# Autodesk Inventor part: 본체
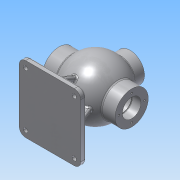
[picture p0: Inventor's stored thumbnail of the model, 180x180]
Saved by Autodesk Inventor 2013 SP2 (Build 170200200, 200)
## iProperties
Created: 2018-06
Part Number: 본체
Material: 알루미늄 6061
Document SubType Name: Modeling
Designer: Administrator
Density: 2.71 g/cm^3
Mass: 1509.84 g
Surface Area: 1154.8 cm^2
Volume: 557.135 cm^3
Author: Administrator
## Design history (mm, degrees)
sketch "스케치1"
  geometry: L1 (-68, 0)-(68, 0); L2 (-42.988, 31)-(-68, 31); L3 (-68, 31)-(-68, 17.5); L4 (-68, 17.5)-(-39.278, 17.5); L5 (42.988, 31)-(68, 31); L6 (68, 31)-(68, 17.5); L7 (68, 17.5)-(39.278, 17.5); A1 r 53 centre (0, 0) between (42.988, 31) and (-42.988, 31); A2 r 43 centre (0, 0) between (39.278, 17.5) and (-39.278, 17.5); 2 further points
  constraints: 14 end point, 4 perpendicular, 4 point on circle, 3 coincident, 2 centre point, 2 horizontal alignment, 2 parallel, 1 horizontal, 1 midpoint, 1 vertical alignment
  dimensions: "d0" = 106 diameter of A1; "d1" = 86 diameter of A2; "d2" = 136 distance of L1.start L1.end; "d3" = 136 distance between parallel lines of L3 L6; "d4" = 62 diameter of L2 L1; "d5" = 35 diameter of L4 L1
revolve "회전1" sketch "스케치1" stored, may be unused: angle "d6" = 90 deg
node "작업 평면1"
sketch "스케치2"
  geometry: L1 (-57.5, -62.5)-(57.5, -62.5); L2 (57.5, -62.5)-(57.5, 62.5); L3 (57.5, 62.5)-(-57.5, 62.5); L4 (-57.5, 62.5)-(-57.5, -62.5); L5 (-57.5, -62.5)-(57.5, 62.5); L6 (57.5, -62.5)-(-57.5, 62.5); 1 further point
  constraints: 12 end point, 2 midpoint, 2 parallel, 1 horizontal, 1 perpendicular
  dimensions: "d8" = 115 distance of L3.end L2.end; "d9" = 125 distance of L2.end L1.end
extrude "돌출1" join sketch "스케치2" distance "d10" = 10; taper "d11" = 0 deg
sketch "스케치4"
  geometry: L1 (57.5, -75)-(-57.5, -75) reference; L2 (33.719, -40.891)-(47.5, -75); L3 (57.5, -85)-(57.5, -75) reference; L4 (-57.5, -85)-(-57.5, -75) reference; L5 (-33.654, -40.944)-(-47.414, -75); L6 (-47.414, -75)-(47.5, -75); A1 r 53 centre (0, 0) between (42.988, 31) and (42.988, -31) reference; 1 further point
  constraints: 6 end point, 2 point on circle, 2 point on line, 1 collinear
  dimensions: "d12" = 22 deg angle of L3 L2; "d13" = 10 distance of L1.start L2.end; "d16" = 10.08634 distance of L1.end L5.end; "d17" = 22 deg angle of L4 L5
node "작업 평면2"
sketch "스케치5"
  geometry: C1 r 27 at (0, 0); 1 further point
  constraints: 1 centre point, 1 coincident
  dimensions: "d19" = 54 diameter of C1
extrude "돌출2" join sketch "스케치5" stored distance "d21" = 10; taper "d22" = 0 deg
hole "구멍1" diameter "d25" = 26; stored, may be unused: countersink angle "d29" = 90 deg, drill point angle "d31" = 0 deg; dims "d26" = 6, "d27" = 4, "d28" = 2, "d30" = 8, "d32" = 10, "d33" = 10
sketch "스케치6" dims "d34" = 45
  geometry: C1 r 31 at (0, 0) reference; C2 r 17.5 at (0, 0) reference; 2 further points
  constraints: 2 vertical alignment, 1 coincident, 2 other
hole "구멍2" sketch "스케치6" at (0, 22.5) diameter "d35" = 3.242; stored, may be unused: countersink angle "d39" = 90 deg, drill point angle "d41" = 118 deg; dims "d36" = 12, "d37" = 4, "d38" = 2, "d40" = 15
sketch "스케치7" dims "d45" = 48
  geometry: C1 r 17.5 at (0, 0) reference; C2 r 31 at (0, 0) reference; 2 further points
  constraints: 2 vertical alignment, 1 coincident, 2 other
hole "구멍3" sketch "스케치7" at (0, 24) diameter "d46" = 3.242; stored, may be unused: countersink angle "d50" = 90 deg, drill point angle "d52" = 118 deg; dims "d47" = 16, "d48" = 4, "d49" = 2, "d51" = 19
sketch "스케치9"
  geometry: L1 (57.5, 62.5)-(-57.5, 62.5) reference; L2 (-4, -52.5)-(4, -52.5); L3 (4, -52.5)-(4, 52.5); L4 (4, 52.5)-(-4, 52.5); L5 (-4, 52.5)-(-4, -52.5); L6 (-4, -52.5)-(4, 52.5); L7 (4, -52.5)-(-4, 52.5); 1 further point
  constraints: 12 end point, 2 midpoint, 2 parallel, 1 horizontal, 1 perpendicular
  dimensions: "d57" = 8 distance of L4.end L3.end; "d58" = 10 distance between parallel lines of L1 L4
extrude "돌출3" join sketch "스케치9" stored distance "d59" = 10; taper "d60" = 0 deg
feature "면 기울기1" dims angle "d61" = 22 deg
sketch "스케치10"
  geometry: L1 (57.5, -62.5)-(57.5, 62.5) reference; L2 (-47.5, 4)-(47.5, 4); L3 (47.5, 4)-(47.5, -4); L4 (47.5, -4)-(-47.5, -4); L5 (-47.5, -4)-(-47.5, 4); L6 (-47.5, 4)-(47.5, -4); L7 (47.5, 4)-(-47.5, -4); 1 further point
  constraints: 12 end point, 2 midpoint, 2 parallel, 1 horizontal, 1 perpendicular
  dimensions: "d62" = 8 distance of L2.end L3.end; "d63" = 10 distance between parallel lines of L1 L3
extrude "돌출4" join sketch "스케치10" stored distance "d64" = 10; taper "d65" = 0 deg
feature "면 기울기2" dims angle "d66" = 22 deg
sketch "스케치11" dims "d67" = 40
  geometry: C1 r 13 at (0, 0) reference; C2 r 27 at (0, 0) reference; 2 further points
  constraints: 2 vertical alignment, 1 coincident, 2 other
hole "구멍4" sketch "스케치11" at (0, 20) diameter "d68" = 3.242; stored, may be unused: countersink angle "d72" = 90 deg, drill point angle "d74" = 118 deg; dims "d69" = 9, "d70" = 4, "d71" = 2, "d73" = 11
sketch "스케치12"
  geometry: L1 (-45.5, -50.5)-(45.5, -50.5); L2 (45.5, -50.5)-(45.5, 50.5); L3 (45.5, 50.5)-(-45.5, 50.5); L4 (-45.5, 50.5)-(-45.5, -50.5); L5 (-45.5, -50.5)-(45.5, 50.5); L6 (45.5, -50.5)-(-45.5, 50.5); 5 further points
  constraints: 12 end point, 4 coincident, 2 midpoint, 2 parallel, 1 horizontal, 1 perpendicular
  dimensions: "d78" = 91 distance of L3.end L2.end; "d79" = 101 distance of L2.end L1.end
hole "구멍5" sketch "스케치12" at (-45.5, 50.5), (45.5, 50.5), (45.5, -50.5), (-45.5, -50.5) diameter "d80" = 8; stored, may be unused: countersink angle "d84" = 90 deg, drill point angle "d86" = 0 deg; dims "d81" = 9, "d82" = 12, "d83" = 3, "d85" = 10
fillet "모깎기1" dims "d87" = 12
sketch "스케치14"
  geometry: 1 further point
node "작업 평면4"
sketch "스케치15"
  geometry: L1 (-1.621, 65)-(1.621, 65) reference; 3 further points
  constraints: 1 coincident, 1 vertical alignment, 1 other
  dimensions: "d93" = 10 distance from line of point (0, 55) L1
feature "엠보싱2" sketch "스케치15" dims "d0" = 106, "d1" = 86, "d2" = 136, "d3" = 136, "d4" = 62, "d5" = 35, "d94" = 0.5, "d95" = 0
node "작업 평면5"
sketch "스케치16"
  geometry: C1 r 18.5 at (0, 0); 1 further point
  constraints: 1 centre point, 1 coincident
  dimensions: "d97" = 37 diameter of C1
extrude "돌출5" cut sketch "스케치16" distance "d98" = 1.75; taper "d99" = 0 deg
fillet "모깎기2" dims "d100" = 3
chamfer "모따기1" distance "d101" = 1; stored, may be unused: second distance "d102" = 2, angle "d103" = 45 deg
fillet "모깎기3" dims "d104" = 3
fillet "모깎기4" dims "d105" = 3
fillet "모깎기5" dims "d106" = 3
fillet "모깎기6" dims "d111" = 3
node "솔리드1"
pattern_circular "원형 패턴1" dims angle "d43" = 360 deg
pattern_circular "원형 패턴2" dims angle "d54" = 360 deg
pattern_circular "원형 패턴3" dims angle "d76" = 360 deg
other parameters: "d7" = -85, "d18" = 65, "d92" = -27, "d96" = -16
